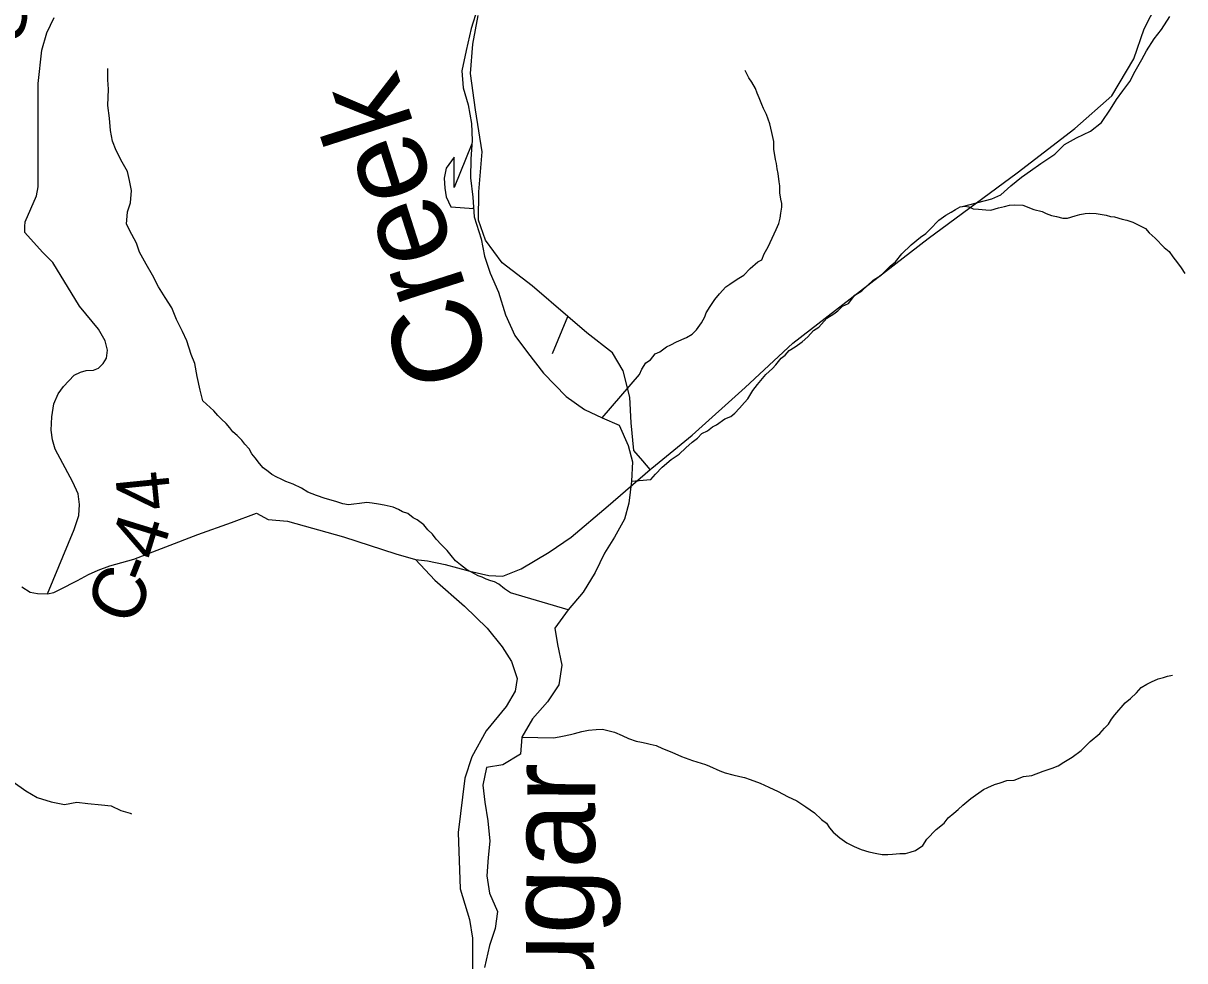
# Model space of a CAD drawing. Extents: x 0 to 34, y 0 to 22.
# Drawn here: x 5.45 to 6.694, y 16.395 to 17.398 of the extents above; entities that cross this region are included whole.
import ezdxf

# ---------------------------------------------------------------- set-up
doc = ezdxf.new("R2010")
doc.units = 0
for name, color, linetype in [('GM_X_County_Road', 7, 'Continuous'), ('GM_X_County_Road_Text', 7, 'Continuous'), ('GM_X_Minor_River', 7, 'Continuous'), ('GM_X_Minor_River_Text', 7, 'Continuous'), ('GM_X_State_Route', 7, 'Continuous'), ('GM_X_Township_Road', 7, 'Continuous')]:
    doc.layers.add(name, color=color, linetype=linetype)

msp = doc.modelspace()

# ---------------------------------------------------------------- linework, layer by layer
at = {"layer": 'GM_X_County_Road'}
for points in [[(5.4762, 16.7875), (5.5048, 16.8563), (5.5097, 16.8714), (5.5104, 16.883), (5.5091, 16.8946), (5.5032, 16.9072), (5.4845, 16.9425), (5.4814, 16.9525), (5.48, 16.9628), (5.4806, 16.977), (5.483, 16.9908), (5.4876, 17.0015), (5.4932, 17.0095), (5.5046, 17.0215), (5.5113, 17.025), (5.5177, 17.0266), (5.5254, 17.027), (5.5306, 17.029), (5.5359, 17.0342), (5.5394, 17.04), (5.5403, 17.0483), (5.5377, 17.0585), (5.5309, 17.071), (5.5105, 17.0955), (5.4819, 17.1421), (5.4708, 17.1532), (5.452, 17.1744), (5.4517, 17.1807), (5.4523, 17.1858), (5.4642, 17.2136), (5.466, 17.2234), (5.4661, 17.3338), (5.4702, 17.3696), (5.4754, 17.3881), (5.4834, 17.4045)], [(5.8701, 16.8242), (5.891, 16.8023), (5.9225, 16.7742), (5.9468, 16.7506), (5.9631, 16.7309), (5.9729, 16.7149), (5.979, 16.697), (5.9767, 16.6834), (5.9672, 16.667), (5.9459, 16.6408), (5.9303, 16.6131), (5.9231, 16.59), (5.9158, 16.5319), (5.918, 16.4715), (5.9279, 16.4388), (5.9313, 16.4187), (5.9313, 16.3944), (5.9308, 16.3677), (5.9294, 16.3385), (5.9297, 16.311), (5.9312, 16.2975), (5.9323, 16.2885), (5.9328, 16.2817)]]:
    msp.add_lwpolyline(points, dxfattribs=at)
at = {"layer": 'GM_X_Minor_River'}
for points in [[(5.9366, 17.4142), (5.9297, 17.3929), (5.9243, 17.3694), (5.9197, 17.3474), (5.9212, 17.3292), (5.9264, 17.311), (5.9301, 17.2912), (5.9308, 17.273), (5.9293, 17.2533), (5.9292, 17.2328), (5.9314, 17.2123), (5.9329, 17.191), (5.9404, 17.1675), (5.9441, 17.1492), (5.9501, 17.131), (5.9591, 17.1105), (5.9666, 17.0862), (5.9764, 17.0641), (5.9899, 17.0459), (6.0073, 17.0238), (6.0314, 16.9987), (6.0511, 16.985), (6.07, 16.9758), (6.0881, 16.9682), (6.0979, 16.9462), (6.1024, 16.9287), (6.1015, 16.9082), (6.0984, 16.8847), (6.0938, 16.8673), (6.0832, 16.8483), (6.0725, 16.8309), (6.0626, 16.8105), (6.0497, 16.7893), (6.0337, 16.7703), (6.0193, 16.7506), (6.0223, 16.7332), (6.0268, 16.7112), (6.0237, 16.6899), (6.0115, 16.6718), (5.9955, 16.6536), (5.9841, 16.6339), (5.9826, 16.6157), (5.9636, 16.6044), (5.9462, 16.6014), (5.9423, 16.5825), (5.9445, 16.5643), (5.9475, 16.5445), (5.9497, 16.5225), (5.9481, 16.5051)], [(6.4557, 17.2024), (6.4871, 17.2106), (6.4969, 17.2147), (6.5075, 17.2242), (6.5189, 17.2337), (6.5287, 17.2405), (6.5397, 17.2481), (6.5545, 17.2583), (6.5651, 17.2686), (6.578, 17.2758), (6.5927, 17.283), (6.6048, 17.2921), (6.6143, 17.3065), (6.6207, 17.3167), (6.6275, 17.3262), (6.6351, 17.3361), (6.6408, 17.3471), (6.648, 17.3596), (6.6529, 17.369), (6.6612, 17.3816), (6.6688, 17.3918), (6.6779, 17.4058)], [(5.6543, 16.9833), (5.6426, 16.994), (5.6395, 17.0057), (5.6365, 17.0202), (5.6339, 17.0342), (5.6301, 17.0437), (5.6252, 17.0585), (5.6206, 17.0683), (5.6142, 17.0812), (5.6093, 17.0938), (5.6021, 17.1048), (5.595, 17.1161), (5.5885, 17.1287), (5.5817, 17.1404), (5.5745, 17.1533), (5.5715, 17.1628), (5.5666, 17.1723), (5.5606, 17.1833), (5.5617, 17.1966), (5.5651, 17.2061), (5.5662, 17.2194), (5.564, 17.23), (5.5617, 17.2398), (5.556, 17.2497), (5.5496, 17.2622), (5.5458, 17.2721), (5.5436, 17.2835), (5.5424, 17.2968), (5.5409, 17.3104), (5.5413, 17.3279), (5.5409, 17.3378), (5.5409, 17.3499)], [(6.07, 16.9758), (6.1099, 17.0223), (6.1123, 17.028), (6.1166, 17.0348), (6.1216, 17.0381), (6.1266, 17.0445), (6.1316, 17.0467), (6.1389, 17.0519), (6.1434, 17.0541), (6.1496, 17.0574), (6.1602, 17.0618), (6.1664, 17.0655), (6.171, 17.07), (6.1764, 17.0775), (6.1799, 17.0842), (6.1815, 17.0884), (6.1858, 17.0952), (6.1905, 17.1027), (6.1955, 17.1087), (6.2025, 17.1162), (6.2067, 17.1191), (6.2144, 17.1243), (6.2216, 17.1288), (6.2286, 17.1359), (6.2367, 17.1429), (6.2409, 17.1452), (6.2436, 17.1516), (6.2479, 17.1591), (6.2562, 17.1776), (6.2593, 17.184), (6.2606, 17.1897), (6.2614, 17.195), (6.2623, 17.2014), (6.2624, 17.2056), (6.2613, 17.2102), (6.2603, 17.217), (6.2601, 17.2243), (6.2594, 17.2285), (6.2584, 17.2376), (6.2573, 17.2426), (6.2567, 17.2483), (6.2556, 17.2525), (6.2539, 17.2635), (6.2537, 17.2719), (6.2516, 17.2814), (6.2495, 17.2906), (6.2459, 17.3009), (6.2426, 17.307), (6.2411, 17.3116), (6.2382, 17.3185), (6.236, 17.3235), (6.2342, 17.3285), (6.2302, 17.3354), (6.2269, 17.34), (6.2232, 17.3477)], [(5.9305, 17.2693), (5.9115, 17.2227), (5.9115, 17.255), (5.9031, 17.2432), (5.9009, 17.2326), (5.9016, 17.222), (5.9031, 17.2125), (5.908, 17.2019), (5.9179, 17.2011), (5.9322, 17.2), (5.9315, 17.2004)], [(6.1015, 16.9082), (6.122, 16.91), (6.127, 16.9157), (6.1343, 16.9231), (6.1439, 16.9313), (6.1524, 16.9369), (6.1597, 16.944), (6.1662, 16.95), (6.172, 16.954), (6.1766, 16.9593), (6.1827, 16.9622), (6.1881, 16.9663), (6.1923, 16.9685), (6.2015, 16.9748), (6.2076, 16.9774), (6.2122, 16.9811), (6.2172, 16.9863), (6.2223, 16.9923), (6.2261, 16.9964), (6.2312, 17.0051), (6.2363, 17.0118), (6.2451, 17.0223), (6.2525, 17.0287), (6.2559, 17.0328), (6.2617, 17.0399), (6.266, 17.0429), (6.2702, 17.0481), (6.2767, 17.0518), (6.284, 17.0574), (6.2902, 17.0626), (6.2964, 17.0693), (6.3021, 17.0731), (6.3106, 17.0828), (6.3179, 17.0872), (6.3225, 17.0906), (6.3275, 17.0954), (6.3336, 17.0984), (6.3406, 17.1074), (6.3482, 17.1118), (6.3602, 17.1234), (6.3686, 17.1286), (6.3782, 17.1383), (6.384, 17.1431), (6.391, 17.1517), (6.401, 17.1611), (6.411, 17.1693), (6.4167, 17.1733), (6.421, 17.1775), (6.4306, 17.1875), (6.4379, 17.1931), (6.4436, 17.1961), (6.4482, 17.199), (6.4532, 17.202), (6.4578, 17.2027), (6.4627, 17.2018), (6.4672, 17.1999), (6.4729, 17.1994), (6.4808, 17.1985), (6.4861, 17.1984), (6.4945, 17.2009), (6.5009, 17.2023), (6.5063, 17.2037), (6.5116, 17.204), (6.5203, 17.2035), (6.5323, 17.1991), (6.541, 17.1967), (6.5455, 17.1947), (6.5512, 17.1927), (6.5564, 17.1915), (6.5632, 17.1899), (6.5681, 17.1898), (6.5765, 17.1923), (6.5815, 17.1937), (6.5872, 17.1948), (6.5917, 17.1951), (6.5989, 17.1946), (6.6095, 17.1929), (6.6144, 17.1917), (6.6185, 17.1912), (6.6268, 17.1888), (6.6317, 17.1876), (6.6381, 17.1856), (6.6517, 17.1785), (6.6558, 17.1742), (6.6621, 17.1684), (6.6718, 17.1584), (6.677, 17.1541), (6.6811, 17.1483), (6.6859, 17.1418), (6.6899, 17.1364), (6.694, 17.1306)], [(6.0337, 16.7703), (6.0337, 16.7703), (5.9717, 16.7887), (5.9654, 16.793), (5.9594, 16.7977), (5.9549, 16.8004), (5.9507, 16.8013), (5.9459, 16.8032), (5.9417, 16.8052), (5.9372, 16.8068), (5.9293, 16.8111), (5.9248, 16.8135), (5.9185, 16.8185), (5.9129, 16.8228), (5.9084, 16.8286), (5.904, 16.834), (5.898, 16.8398), (5.8924, 16.8459), (5.8884, 16.8513), (5.8832, 16.856), (5.8791, 16.8614), (5.872, 16.8668), (5.8678, 16.8688), (5.8619, 16.8734), (5.8562, 16.8754), (5.8521, 16.8778), (5.8461, 16.8802), (5.8367, 16.8826), (5.8306, 16.8835), (5.8238, 16.8847), (5.8181, 16.8852), (5.8102, 16.8842), (5.8041, 16.8835), (5.7984, 16.8829), (5.7924, 16.8837), (5.7848, 16.8865), (5.7735, 16.8897), (5.7641, 16.8929), (5.7547, 16.8965), (5.748, 16.9008), (5.7393, 16.9051), (5.7314, 16.9079), (5.7262, 16.9103), (5.7216, 16.9123), (5.7164, 16.9154), (5.7123, 16.9185), (5.7071, 16.9224), (5.703, 16.927), (5.6985, 16.9332), (5.6948, 16.9374), (5.6919, 16.9428), (5.6874, 16.9478), (5.6841, 16.9521), (5.6793, 16.9571), (5.6744, 16.961), (5.6714, 16.9652), (5.6674, 16.9698), (5.6625, 16.9745), (5.6584, 16.9783), (5.6543, 16.9833)], [(5.9841, 16.6339), (6.0182, 16.6333), (6.0277, 16.6351), (6.0361, 16.6368), (6.0403, 16.6379), (6.0483, 16.64), (6.0555, 16.6414), (6.0635, 16.6424), (6.0703, 16.6427), (6.0775, 16.6407), (6.0831, 16.6395), (6.0914, 16.6359), (6.0982, 16.6327), (6.1064, 16.6299), (6.1121, 16.6287), (6.117, 16.6275), (6.1215, 16.6266), (6.1279, 16.625), (6.1347, 16.6219), (6.1445, 16.6179), (6.155, 16.6135), (6.1667, 16.6092), (6.1712, 16.6076), (6.1806, 16.6047), (6.1851, 16.6028), (6.196, 16.598), (6.2017, 16.596), (6.21, 16.5936), (6.2175, 16.592), (6.2224, 16.5907), (6.2284, 16.5887), (6.239, 16.5848), (6.2484, 16.5804), (6.2585, 16.5757), (6.2683, 16.5706), (6.2784, 16.5659), (6.2882, 16.5596), (6.2975, 16.553), (6.305, 16.5457), (6.3102, 16.5418), (6.3135, 16.5368), (6.3172, 16.5322), (6.3243, 16.5263), (6.3318, 16.5209), (6.34, 16.517), (6.3472, 16.5138), (6.3555, 16.5114), (6.3642, 16.5093), (6.3698, 16.5085), (6.3759, 16.5084), (6.3808, 16.5087), (6.3888, 16.5093), (6.3948, 16.5096), (6.3998, 16.511), (6.4055, 16.5128), (6.4132, 16.518), (6.4178, 16.5247), (6.4275, 16.5352), (6.4363, 16.5419), (6.4406, 16.5475), (6.4464, 16.5528), (6.4513, 16.5565), (6.456, 16.5613), (6.4648, 16.5684), (6.4782, 16.578), (6.4828, 16.5802), (6.4901, 16.5835), (6.4962, 16.585), (6.5034, 16.5875), (6.511, 16.5881), (6.5213, 16.5918), (6.53, 16.5931), (6.5422, 16.5975), (6.5517, 16.6007), (6.5582, 16.6033), (6.5644, 16.6074), (6.5732, 16.6125), (6.5828, 16.6196), (6.5924, 16.6293), (6.6028, 16.6379), (6.6078, 16.6435), (6.612, 16.648), (6.6152, 16.6532), (6.619, 16.6581), (6.6299, 16.6708), (6.6356, 16.6753), (6.6422, 16.6816), (6.6472, 16.6872), (6.6533, 16.6906), (6.6583, 16.6931), (6.6652, 16.6964), (6.6709, 16.6979), (6.6754, 16.6993), (6.6808, 16.7004)], [(5.4395, 16.5862), (5.4531, 16.5767), (5.4652, 16.5694), (5.4799, 16.5648), (5.4943, 16.5621), (5.5076, 16.5643), (5.5193, 16.5631), (5.534, 16.5616), (5.5443, 16.5604), (5.5548, 16.5554), (5.5647, 16.5527), (5.5662, 16.552)], [(5.9481, 16.5051), (5.9466, 16.4854), (5.9495, 16.4671), (5.9578, 16.4474), (5.9555, 16.4292), (5.9494, 16.411), (5.944, 16.3875)]]:
    msp.add_lwpolyline(points, dxfattribs=at)
at = {"layer": 'GM_X_State_Route'}
msp.add_lwpolyline([(5.4486, 16.7949), (5.4574, 16.7893), (5.4653, 16.7877), (5.4762, 16.7875), (5.4828, 16.7889), (5.4895, 16.792), (5.5081, 16.8017), (5.5201, 16.8083), (5.5302, 16.8129), (5.543, 16.8176), (5.5684, 16.8246), (5.6372, 16.8512), (5.673, 16.8637), (5.6998, 16.874), (5.7123, 16.867), (5.7331, 16.8652), (5.7931, 16.8486), (5.849, 16.8305), (5.8701, 16.8242), (5.883, 16.8229), (5.9019, 16.8189), (5.9283, 16.8117), (5.9487, 16.8073), (5.9638, 16.8064), (5.9833, 16.8142), (6.0134, 16.832), (6.0367, 16.8481), (6.0765, 16.8818), (6.1215, 16.9207), (6.1232, 16.9222), (6.1665, 16.9574), (6.2231, 17.0083), (6.2741, 17.0559), (6.419, 17.1681), (6.5142, 17.2384), (6.5761, 17.2859), (6.6156, 17.3208), (6.6392, 17.3604), (6.6505, 17.3925), (6.6909, 17.4721)], dxfattribs=at)
at = {"layer": 'GM_X_Township_Road'}
msp.add_line((6.0168, 17.0449), (6.0334, 17.0844), dxfattribs=at)
msp.add_lwpolyline([(6.1215, 16.9207), (6.1136, 16.9299), (6.1038, 16.9409), (6.1011, 16.9705), (6.0996, 16.9979), (6.0925, 17.0264), (6.0811, 17.0454), (6.0537, 17.067), (6.0334, 17.0844), (5.9949, 17.1172), (5.963, 17.1419), (5.9452, 17.1663), (5.9376, 17.1875), (5.938, 17.2179), (5.9415, 17.2609), (5.9343, 17.3057), (5.929, 17.3445), (5.9317, 17.376), (5.9374, 17.4068)], dxfattribs=at)

# ---------------------------------------------------------------- texts
at = {"layer": 'GM_X_County_Road_Text'}
for s, rotation, p in [('S', 80.7083, (5.4492, 17.3759)), ('4', 95.7674, (5.6092, 16.8791)), ('4', 72.8156, (5.5964, 16.8211)), ('C', 68.1149, (5.5687, 16.7513)), ('-', 68.4668, (5.5863, 16.795))]:
    msp.add_text(s, height=0.0568, rotation=rotation, dxfattribs=at).set_placement(p)
at = {"layer": 'GM_X_Minor_River_Text'}
for s, height, rotation, p in [('Creek', 0.09474, 107.753, (5.9529, 17.0268)), ('Sugar', 0.09469, 89.4916, (6.0598, 16.2678))]:
    msp.add_text(s, height=height, rotation=rotation, dxfattribs=at).set_placement(p)

doc.saveas('drawing.dxf')
